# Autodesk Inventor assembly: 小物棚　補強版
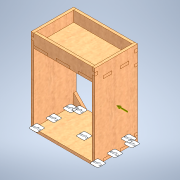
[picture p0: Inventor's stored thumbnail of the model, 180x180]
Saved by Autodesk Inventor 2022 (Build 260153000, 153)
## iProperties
Created: 2024-12
Part Number: 小物棚　補強版
Document SubType Name: Assembly
Designer: shimizu
Mass: 24.2 g
Surface Area: 281.014 cm^2
Volume: 30.25 cm^3
Density: 0.8 g/cm^3
Author: shimizu
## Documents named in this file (6)
- C:\Users\shimizu\Documents\卒論2024\3DCAD\小物棚 - 補強版\組立図\小物棚　補強版.iam
- C:\Users\shimizu\Documents\卒論2024\3DCAD\小物棚 - 補強版\部品図\底板.ipt
- C:\Users\shimizu\Documents\卒論2024\3DCAD\小物棚 - 補強版\部品図\側板.ipt
- C:\Users\shimizu\Documents\卒論2024\3DCAD\小物棚 - 補強版\部品図\天板.ipt
- C:\Users\shimizu\Documents\卒論2024\3DCAD\小物棚 - 補強版\部品図\側板②.ipt
- C:\Users\shimizu\Documents\卒論2024\3DCAD\小物棚 - 補強版\部品図\補強.ipt
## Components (10 placed, 5 different names)
1. 底板:1 — メイト:1, フラッシュ:1, フラッシュ:2, メイト:2, フラッシュ:3, フラッシュ:4, フラッシュ:13, フラッシュ:16
2. 側板:1 — メイト:2, フラッシュ:3, フラッシュ:4, メイト:4, フラッシュ:7, フラッシュ:9, メイト:8, フラッシュ:12, メイト:11, フラッシュ:15
3. 側板:2 — メイト:1, フラッシュ:1, フラッシュ:2, フラッシュ:5, フラッシュ:6, メイト:3, フラッシュ:8, フラッシュ:10, メイト:6, フラッシュ:11, メイト:10, フラッシュ:14
4. 天板:1 — フラッシュ:5, フラッシュ:6, メイト:3, メイト:5
5. 側板②:1 — メイト:4, フラッシュ:7, フラッシュ:8
6. 側板②:2 — メイト:5, フラッシュ:9, フラッシュ:10, メイト:7, メイト:9
7. 補強:1 — メイト:6, フラッシュ:11, メイト:7
8. 補強:2 — メイト:10, フラッシュ:13, フラッシュ:14
9. 補強:3 — メイト:11, フラッシュ:15, フラッシュ:16
10. 補強:4 — メイト:8, フラッシュ:12, メイト:9
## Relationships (27: Flush 16, Mate 11)
- メイト:1 [Mate]: 底板:1 ↔ 側板:2
- フラッシュ:1 [Flush]: 底板:1 ↔ 側板:2
- フラッシュ:2 [Flush]: 底板:1 ↔ 側板:2
- メイト:2 [Mate]: 底板:1 ↔ 側板:1
- フラッシュ:3 [Flush]: 底板:1 ↔ 側板:1
- フラッシュ:4 [Flush]: 底板:1 ↔ 側板:1
- フラッシュ:5 [Flush]: 側板:2 ↔ 天板:1
- フラッシュ:6 [Flush]: 側板:2 ↔ 天板:1
- メイト:3 [Mate]: 側板:2 ↔ 天板:1
- メイト:4 [Mate]: 側板:1 ↔ 側板②:1
- フラッシュ:7 [Flush]: 側板:1 ↔ 側板②:1
- フラッシュ:8 [Flush]: 側板:2 ↔ 側板②:1
- メイト:5 [Mate]: 天板:1 ↔ 側板②:2
- フラッシュ:9 [Flush]: 側板:1 ↔ 側板②:2
- フラッシュ:10 [Flush]: 側板:2 ↔ 側板②:2
- メイト:6 [Mate]: 側板:2 ↔ 補強:1
- フラッシュ:11 [Flush]: 側板:2 ↔ 補強:1
- メイト:7 [Mate]: 側板②:2 ↔ 補強:1
- メイト:8 [Mate]: 側板:1 ↔ 補強:4
- フラッシュ:12 [Flush]: 側板:1 ↔ 補強:4
- メイト:9 [Mate]: 側板②:2 ↔ 補強:4
- メイト:10 [Mate]: 側板:2 ↔ 補強:2
- フラッシュ:13 [Flush]: 底板:1 ↔ 補強:2
- フラッシュ:14 [Flush]: 側板:2 ↔ 補強:2
- メイト:11 [Mate]: 側板:1 ↔ 補強:3
- フラッシュ:15 [Flush]: 側板:1 ↔ 補強:3
- フラッシュ:16 [Flush]: 底板:1 ↔ 補強:3
## Named parameters: sa_0 = 50000 mm
